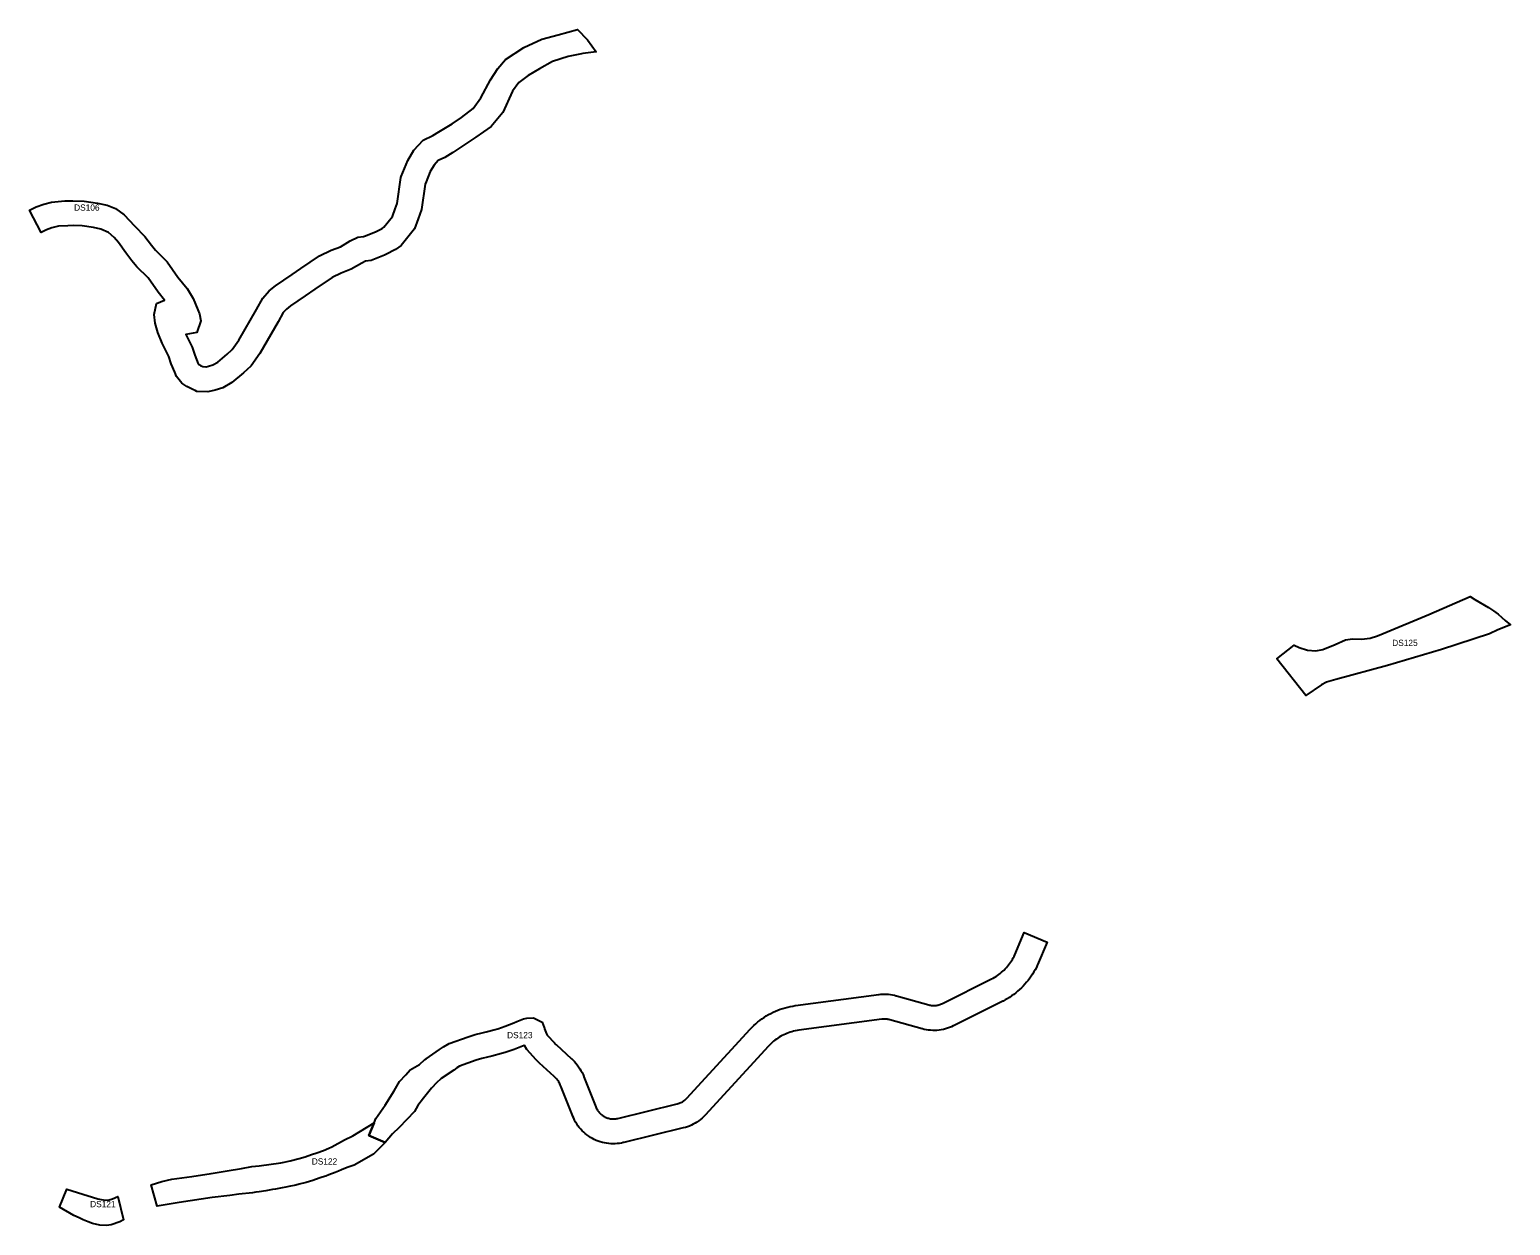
# Model space of a CAD drawing. Extents: x -546777 to -486947, y -1193757 to -1133234.
# Drawn here: x -517108 to -505213, y -1188442 to -1178838 of the extents above; entities that cross this region are included whole.
import ezdxf

# ---------------------------------------------------------------- set-up
doc = ezdxf.new("R2010")
doc.units = 0
doc.layers.add('01 - silnice', color=7, linetype='Continuous')

msp = doc.modelspace()

# ---------------------------------------------------------------- linework, layer by layer
at = {"layer": '01 - silnice'}
for points in [[(-515331.83, -1181540.9), (-515389.82, -1181595.02), (-515482.74, -1181672.46), (-515554.98, -1181713.74), (-515618.28, -1181734.84), (-515675.87, -1181746.35), (-515764.51, -1181743.19), (-515778.82, -1181736.3), (-515791.23, -1181730.32), (-515843.67, -1181705.07), (-515886.39, -1181676.59), (-515929.21, -1181623.06), (-515942.42, -1181590.42), (-515970.06, -1181522.15), (-515988.84, -1181463.93), (-516042.9, -1181355.81), (-516079, -1181270.07), (-516098.36, -1181195.03), (-516107.29, -1181126.57), (-516089.74, -1181038.81), (-516023.43, -1181010.39), (-516075.52, -1180946.73), (-516156.62, -1180832.8), (-516246.24, -1180743.18), (-516286.74, -1180693.68), (-516334.06, -1180630.56), (-516394.1, -1180546.45), (-516428.72, -1180507.71), (-516474.89, -1180466.49), (-516536.71, -1180440.94), (-516596.06, -1180426.93), (-516686.73, -1180414.56), (-516756.79, -1180411.26), (-516802.13, -1180412.91), (-516874.67, -1180417.86), (-516929.07, -1180429.4), (-516971.94, -1180445.06), (-517016.45, -1180466.49), (-517107.95, -1180287.62), (-517056.01, -1180262.07), (-516993.37, -1180238.99), (-516931.55, -1180224.15), (-516824.39, -1180211.78), (-516760.09, -1180211.78), (-516670.24, -1180216.73), (-516562.26, -1180231.57), (-516485.6, -1180247.23), (-516418.83, -1180275.25), (-516349.59, -1180324.71), (-516265.74, -1180414.32), (-516181.88, -1180500.13), (-516129.26, -1180570.32), (-516097.76, -1180608.82), (-516003.38, -1180703.2), (-515916.48, -1180825.27), (-515841.35, -1180917.1), (-515794.96, -1180998.1), (-515757.69, -1181087.54), (-515743.88, -1181120.68), (-515732.73, -1181176.43), (-515764.17, -1181270.74), (-515854.31, -1181285.77), (-515803.16, -1181388.07), (-515781.94, -1181453.84), (-515754.79, -1181520.94), (-515749.61, -1181527.41), (-515744.33, -1181530.93), (-515736.37, -1181534.76), (-515730.34, -1181537.66), (-515715.49, -1181544.81), (-515692.13, -1181545.65), (-515691.03, -1181545.42), (-515669.72, -1181541.16), (-515637.02, -1181530.26), (-515597.26, -1181507.54), (-515522.18, -1181444.98), (-515484.53, -1181409.84), (-515480.97, -1181406.52), (-515427.79, -1181330.89), (-515285.03, -1181086.74), (-515234.05, -1180993.64), (-515182.89, -1180937.09), (-515131.57, -1180895.69), (-514998.15, -1180804.89), (-514928.26, -1180757.33), (-514778.31, -1180655.28), (-514685.94, -1180610.22), (-514611.49, -1180581.59), (-514532.91, -1180535.59), (-514470.39, -1180505.68), (-514426.97, -1180498.45), (-514418.44, -1180497.03), (-514328.97, -1180462.61), (-514274.79, -1180434.71), (-514261.81, -1180425.19), (-514192.37, -1180338.38), (-514170.57, -1180278.4), (-514154.35, -1180233.74), (-514125.32, -1180025.85), (-514121.96, -1180017.6), (-514069.87, -1179889.54), (-514020.55, -1179805.84), (-513946.31, -1179726.52), (-513868.04, -1179688.18), (-513819.95, -1179658.98), (-513712.81, -1179593.37), (-513639.16, -1179544.27), (-513544.23, -1179472.25), (-513483.67, -1179387.14), (-513405.11, -1179241.48), (-513346.19, -1179149.82), (-513285.63, -1179077.81), (-513136.69, -1178982.88), (-512993.33, -1178914.87), (-512863.16, -1178879.09), (-512705.58, -1178837.98), (-512626.42, -1178920.2), (-512557.9, -1179017.64), (-512663.53, -1179030.84), (-512673.61, -1179032.1), (-512782.47, -1179052.65), (-512906.55, -1179094.52), (-513012.92, -1179152.05), (-513103.96, -1179205.47), (-513177.61, -1179262.75), (-513228.35, -1179333.13), (-513305.27, -1179503.35), (-513400.2, -1179616.28), (-513524.59, -1179703.02), (-513603.15, -1179755.4), (-513708.05, -1179825.02), (-513771.96, -1179863.82), (-513825.37, -1179889.98), (-513859.45, -1179926.4), (-513890.13, -1179978.46), (-513923.24, -1180059.86), (-513930.68, -1180078.15), (-513959.18, -1180282.26), (-513986.4, -1180357.16), (-514015.63, -1180437.62), (-514122.18, -1180570.81), (-514169.21, -1180605.29), (-514247.03, -1180645.38), (-514256.17, -1180648.9), (-514365.56, -1180690.97), (-514409.61, -1180698.31), (-514439.09, -1180712.41), (-514524.51, -1180762.41), (-514606.05, -1180793.78), (-514677.69, -1180828.72), (-514815.74, -1180922.67), (-514894.29, -1180976.13), (-515012.32, -1181056.46), (-515045.11, -1181082.91), (-515069.95, -1181110.36), (-515110.96, -1181185.26), (-515259.37, -1181439.08), (-515329.31, -1181538.55)], [(-505381.42, -1183689.92), (-505766.15, -1183817.9), (-506200.8, -1183944.46), (-506614.11, -1184057.48), (-506689.27, -1184078.84), (-506731.33, -1184099.54), (-506856.84, -1184186.33), (-507087.83, -1183891.92), (-506950.97, -1183781.1), (-506910.25, -1183800.46), (-506843.49, -1183822.49), (-506776.73, -1183826.49), (-506719.32, -1183816.48), (-506620.51, -1183777.09), (-506537.06, -1183738.37), (-506481.65, -1183731.69), (-506408.22, -1183732.36), (-506340.12, -1183725.02), (-506280.7, -1183707.66), (-506233.97, -1183688.3), (-505868.65, -1183535.38), (-505536.59, -1183389.79), (-505498.92, -1183415.97), (-505388.44, -1183479.83), (-505347.58, -1183506.65), (-505309.9, -1183533.47), (-505282.44, -1183559.65), (-505255.62, -1183583.27), (-505212.84, -1183618.4), (-505312.45, -1183659.26)], [(-514251.17, -1187776.41), (-514383.59, -1187720.75), (-514341.01, -1187618.4), (-514325.99, -1187583.74), (-514253.09, -1187477.03), (-514180.16, -1187361.88), (-514137.94, -1187285.12), (-514086.13, -1187231.38), (-514049.66, -1187193), (-513976.07, -1187149.38), (-513932.31, -1187110.79), (-513922.24, -1187102.99), (-513814.33, -1187029.91), (-513783.39, -1187007.64), (-513737.43, -1186981.55), (-513584.31, -1186926.24), (-513529.53, -1186908.75), (-513472.98, -1186894.62), (-513440.97, -1186888.08), (-513369.46, -1186868.91), (-513346.85, -1186863.08), (-513287.45, -1186841.89), (-513218.85, -1186814.52), (-513193.76, -1186805.32), (-513139.28, -1186783.65), (-513114.39, -1186778.54), (-513060.96, -1186774.4), (-512990.63, -1186810.96), (-512975.16, -1186851.71), (-512973.18, -1186857.16), (-512971.01, -1186862.66), (-512955.89, -1186902.25), (-512949.5, -1186913.12), (-512891.41, -1186976.54), (-512885.55, -1186982.69), (-512879.98, -1186988.07), (-512877.41, -1186990.38), (-512876.71, -1186991.01), (-512757.21, -1187100.31), (-512755.48, -1187101.93), (-512743.98, -1187112.96), (-512731.62, -1187125.98), (-512719.98, -1187139.32), (-512708.52, -1187153.61), (-512698, -1187168.26), (-512688.01, -1187183.31), (-512678.76, -1187199), (-512670.18, -1187214.96), (-512662.47, -1187231.31), (-512656.45, -1187245.4), (-512655.46, -1187247.8), (-512558.97, -1187490.8), (-512555.55, -1187498.76), (-512552.21, -1187505.63), (-512548.74, -1187511.97), (-512544.91, -1187518.16), (-512540.53, -1187524.55), (-512536.1, -1187530.42), (-512531.45, -1187535.93), (-512526.36, -1187541.39), (-512521.04, -1187546.59), (-512515.41, -1187551.55), (-512509.66, -1187556.17), (-512503.59, -1187560.53), (-512497.33, -1187564.63), (-512491.15, -1187568.21), (-512484.75, -1187571.49), (-512477.74, -1187574.66), (-512470.63, -1187577.5), (-512463.66, -1187579.89), (-512456.68, -1187581.9), (-512449.65, -1187583.54), (-512442.32, -1187584.86), (-512434.94, -1187585.83), (-512427.53, -1187586.43), (-512420, -1187586.67), (-512412.56, -1187586.55), (-512405.5, -1187586.09), (-512398.05, -1187585.18), (-512390.3, -1187583.91), (-512381.98, -1187582.13), (-511905.46, -1187465.66), (-511897.37, -1187463.46), (-511890.55, -1187461.23), (-511883.53, -1187458.54), (-511876.49, -1187455.46), (-511869.92, -1187452.24), (-511863.57, -1187448.68), (-511857.3, -1187444.78), (-511851.41, -1187440.69), (-511845.59, -1187436.2), (-511840.03, -1187431.48), (-511834.51, -1187426.26), (-511828.39, -1187420), (-511318.93, -1186865.63), (-511317.71, -1186864.33), (-511304.59, -1186850.56), (-511289.59, -1186835.79), (-511274.12, -1186821.77), (-511258.43, -1186808.33), (-511241.94, -1186795.24), (-511225.11, -1186782.86), (-511208.12, -1186771.21), (-511190.46, -1186759.92), (-511172.47, -1186749.37), (-511154.11, -1186739.34), (-511135.51, -1186730.16), (-511116.55, -1186721.4), (-511097.09, -1186713.42), (-511077.74, -1186706.14), (-511057.96, -1186699.54), (-511037.85, -1186693.52), (-511017.61, -1186688.34), (-510997.41, -1186683.83), (-510976.92, -1186679.99), (-510958.13, -1186677.14), (-510956.29, -1186676.87), (-510285.89, -1186587.67), (-510283.35, -1186587.37), (-510269.95, -1186585.93), (-510254.75, -1186584.98), (-510238.99, -1186584.56), (-510222.93, -1186584.99), (-510207.15, -1186586.11), (-510191.57, -1186587.94), (-510176.05, -1186590.45), (-510160.61, -1186593.68), (-510147.52, -1186597.04), (-510145.46, -1186597.6), (-509885.4, -1186670.35), (-509877.23, -1186672.41), (-509870, -1186673.84), (-509862.34, -1186674.98), (-509855.06, -1186675.76), (-509848.06, -1186676.1), (-509840.25, -1186676.1), (-509832.91, -1186675.8), (-509825.92, -1186675.12), (-509818.3, -1186673.98), (-509811.08, -1186672.61), (-509804.16, -1186670.87), (-509796.91, -1186668.7), (-509790.04, -1186666.27), (-509783.19, -1186663.45), (-509775.4, -1186659.8), (-509380.46, -1186462.08), (-509367.54, -1186455.32), (-509355.63, -1186448.6), (-509344.17, -1186441.57), (-509332.62, -1186433.92), (-509321.65, -1186426.19), (-509310.99, -1186417.98), (-509300.2, -1186409.15), (-509289.75, -1186400), (-509279.84, -1186390.81), (-509270.47, -1186381.36), (-509261.28, -1186371.45), (-509252.21, -1186360.92), (-509243.53, -1186350.31), (-509235.48, -1186339.58), (-509227.61, -1186328.41), (-509220.13, -1186316.9), (-509212.93, -1186305.1), (-509206.42, -1186293.5), (-509200.13, -1186281.23), (-509194.5, -1186269.43), (-509119.58, -1186090.5), (-508935.1, -1186167.74), (-509010.96, -1186348.92), (-509012.95, -1186353.36), (-509020.87, -1186369.97), (-509030.17, -1186388.1), (-509040.27, -1186406.1), (-509050.87, -1186423.5), (-509061.99, -1186440.59), (-509073.72, -1186457.22), (-509086.07, -1186473.69), (-509098.99, -1186489.48), (-509112.12, -1186504.75), (-509126.13, -1186519.84), (-509140.76, -1186534.59), (-509155.85, -1186548.59), (-509170.99, -1186561.85), (-509186.61, -1186574.62), (-509202.95, -1186587.21), (-509219.78, -1186599.07), (-509236.63, -1186610.23), (-509254.17, -1186621), (-509272.05, -1186631.08), (-509288.54, -1186639.71), (-509290.13, -1186640.52), (-509687.03, -1186839.22), (-509689.38, -1186840.36), (-509702.61, -1186846.55), (-509718.56, -1186853.13), (-509734.89, -1186858.9), (-509751.03, -1186863.73), (-509767.92, -1186867.99), (-509784.9, -1186871.22), (-509801.48, -1186873.68), (-509819.09, -1186875.4), (-509836.15, -1186876.1), (-509852.94, -1186876.1), (-509870.54, -1186875.24), (-509887.66, -1186873.42), (-509904.19, -1186870.96), (-509921.16, -1186867.59), (-509935.54, -1186863.97), (-509938.04, -1186863.3), (-510198.31, -1186790.49), (-510205.98, -1186788.52), (-510212.55, -1186787.15), (-510219.23, -1186786.06), (-510225.85, -1186785.29), (-510232.67, -1186784.8), (-510239.01, -1186784.64), (-510245.85, -1186784.82), (-510253.05, -1186785.27), (-510260.78, -1186786.09), (-510928.99, -1186875), (-510943.48, -1186877.21), (-510957.19, -1186879.77), (-510970.99, -1186882.86), (-510984.35, -1186886.28), (-510997.64, -1186890.26), (-511010.86, -1186894.66), (-511023.91, -1186899.58), (-511036.64, -1186904.8), (-511049.29, -1186910.64), (-511061.89, -1186916.86), (-511073.92, -1186923.43), (-511085.94, -1186930.48), (-511097.68, -1186937.99), (-511109.29, -1186945.94), (-511120.45, -1186954.16), (-511131.17, -1186962.66), (-511141.88, -1186971.83), (-511152.21, -1186981.21), (-511162.01, -1186990.84), (-511172.27, -1187001.62), (-511682.17, -1187556.46), (-511684.28, -1187558.69), (-511694.29, -1187568.94), (-511706.56, -1187580.52), (-511719.61, -1187591.6), (-511733.19, -1187602.1), (-511747.49, -1187612.02), (-511761.83, -1187620.92), (-511776.88, -1187629.36), (-511792.3, -1187636.93), (-511807.67, -1187643.66), (-511823.65, -1187649.77), (-511840.03, -1187655.14), (-511856.76, -1187659.64), (-512335.86, -1187776.74), (-512338.59, -1187777.37), (-512353.1, -1187780.48), (-512369.75, -1187783.22), (-512386.89, -1187785.31), (-512404.44, -1187786.45), (-512421.6, -1187786.73), (-512438.87, -1187786.17), (-512456.06, -1187784.77), (-512473.08, -1187782.54), (-512490.15, -1187779.46), (-512507.12, -1187775.5), (-512523.74, -1187770.71), (-512540.17, -1187765.1), (-512556.06, -1187758.74), (-512571.64, -1187751.7), (-512587.05, -1187743.79), (-512602.27, -1187734.97), (-512616.81, -1187725.47), (-512630.74, -1187715.43), (-512644.19, -1187704.65), (-512657.16, -1187693.21), (-512669.44, -1187681.21), (-512681.15, -1187668.67), (-512692.5, -1187655.18), (-512702.87, -1187641.45), (-512712.48, -1187627.44), (-512721.66, -1187612.63), (-512729.99, -1187597.37), (-512737.45, -1187582.04), (-512743.27, -1187568.49), (-512744.34, -1187565.9), (-512840.86, -1187322.81), (-512844.93, -1187313.29), (-512848.82, -1187305.04), (-512853.04, -1187297.2), (-512857.59, -1187289.49), (-512862.6, -1187281.94), (-512867.87, -1187274.59), (-512873.41, -1187267.68), (-512879.57, -1187260.62), (-512885.82, -1187254.04), (-512893.07, -1187247.09), (-513011.34, -1187138.91), (-513016.22, -1187134.53), (-513027.45, -1187123.71), (-513037.59, -1187113.06), (-513113.7, -1187029.95), (-513133.37, -1186998.1), (-513134.01, -1186996.43), (-513147.35, -1187001.32), (-513216.76, -1187029.02), (-513288.17, -1187054.49), (-513318.6, -1187062.34), (-513395.03, -1187082.83), (-513428.71, -1187089.7), (-513474.82, -1187101.23), (-513519.91, -1187115.62), (-513653.48, -1187163.88), (-513675.31, -1187176.27), (-513699.83, -1187193.91), (-513802.45, -1187263.41), (-513807.07, -1187267), (-513837.38, -1187293.74), (-513880.6, -1187338.95), (-513901.98, -1187365.35), (-513943.89, -1187419.91), (-513988.06, -1187478.06), (-514016.9, -1187526.01), (-514139.86, -1187655.51), (-514193.6, -1187707.32)], [(-514251.17, -1187776.41), (-514345.2, -1187868.53), (-514500.85, -1187959.09), (-514556.67, -1187977.55), (-514602.19, -1187996.08), (-514626.25, -1188005.75), (-514652.13, -1188017.01), (-514704.06, -1188035.7), (-514728.74, -1188045.57), (-514756.86, -1188055.63), (-514782.85, -1188063.9), (-514833.4, -1188080.67), (-514887.42, -1188097.54), (-514941.96, -1188112.03), (-514968.99, -1188118.73), (-515024.5, -1188130.57), (-515051, -1188135.92), (-515078.02, -1188140.95), (-515131.59, -1188150.4), (-515157.7, -1188154.83), (-515211.41, -1188163.92), (-515264.24, -1188171.39), (-515289.79, -1188175.52), (-515316.26, -1188179.61), (-515427.58, -1188190.94), (-515500.51, -1188200.53), (-515641.31, -1188217.96), (-515907.74, -1188259.35), (-516084.5, -1188287.8), (-516130.2, -1188117.08), (-516044.84, -1188088.63), (-515964.93, -1188071.95), (-515803.72, -1188048.92), (-515648.2, -1188023.96), (-515522.32, -1188004.13), (-515406.47, -1187983.67), (-515322.03, -1187968.32), (-515264.46, -1187962.56), (-515089.08, -1187939.57), (-515063.89, -1187934.49), (-515015.1, -1187924.1), (-514942.93, -1187905.38), (-514895.37, -1187890.51), (-514844.79, -1187873.73), (-514799.59, -1187858.5), (-514747.85, -1187839.1), (-514703.45, -1187821.23), (-514678.99, -1187811.39), (-514579.34, -1187755.3), (-514510.25, -1187722.67), (-514341.01, -1187618.4), (-514383.59, -1187720.75)], [(-516533.89, -1188234.62), (-516494.43, -1188238.46), (-516468.67, -1188236.26), (-516441.27, -1188229.14), (-516397.97, -1188211.05), (-516353.02, -1188397.95), (-516382.07, -1188413.84), (-516453.87, -1188436.86), (-516489.5, -1188441.79), (-516544.85, -1188439.6), (-516603.67, -1188426.76), (-516638.4, -1188412.79), (-516676.88, -1188396.09), (-516710.96, -1188381.03), (-516753.35, -1188362.09), (-516868.22, -1188294.36), (-516807.93, -1188149.67), (-516723.53, -1188177.07), (-516561.27, -1188228.24)]]:
    msp.add_lwpolyline(points, close=True, dxfattribs=at)

# ---------------------------------------------------------------- texts
for s, p in [('DS106', (-516750.39, -1180292.16)), ('DS125', (-506162.24, -1183788.06)), ('DS123', (-513272.36, -1186938.61)), ('DS122', (-514841.42, -1187953.1))]:
    msp.add_text(s, height=50, rotation=360, dxfattribs=at).set_placement(p)
msp.add_text('DS121', height=50, dxfattribs=at).set_placement((-516621.75, -1188295.73))

doc.saveas('drawing.dxf')
